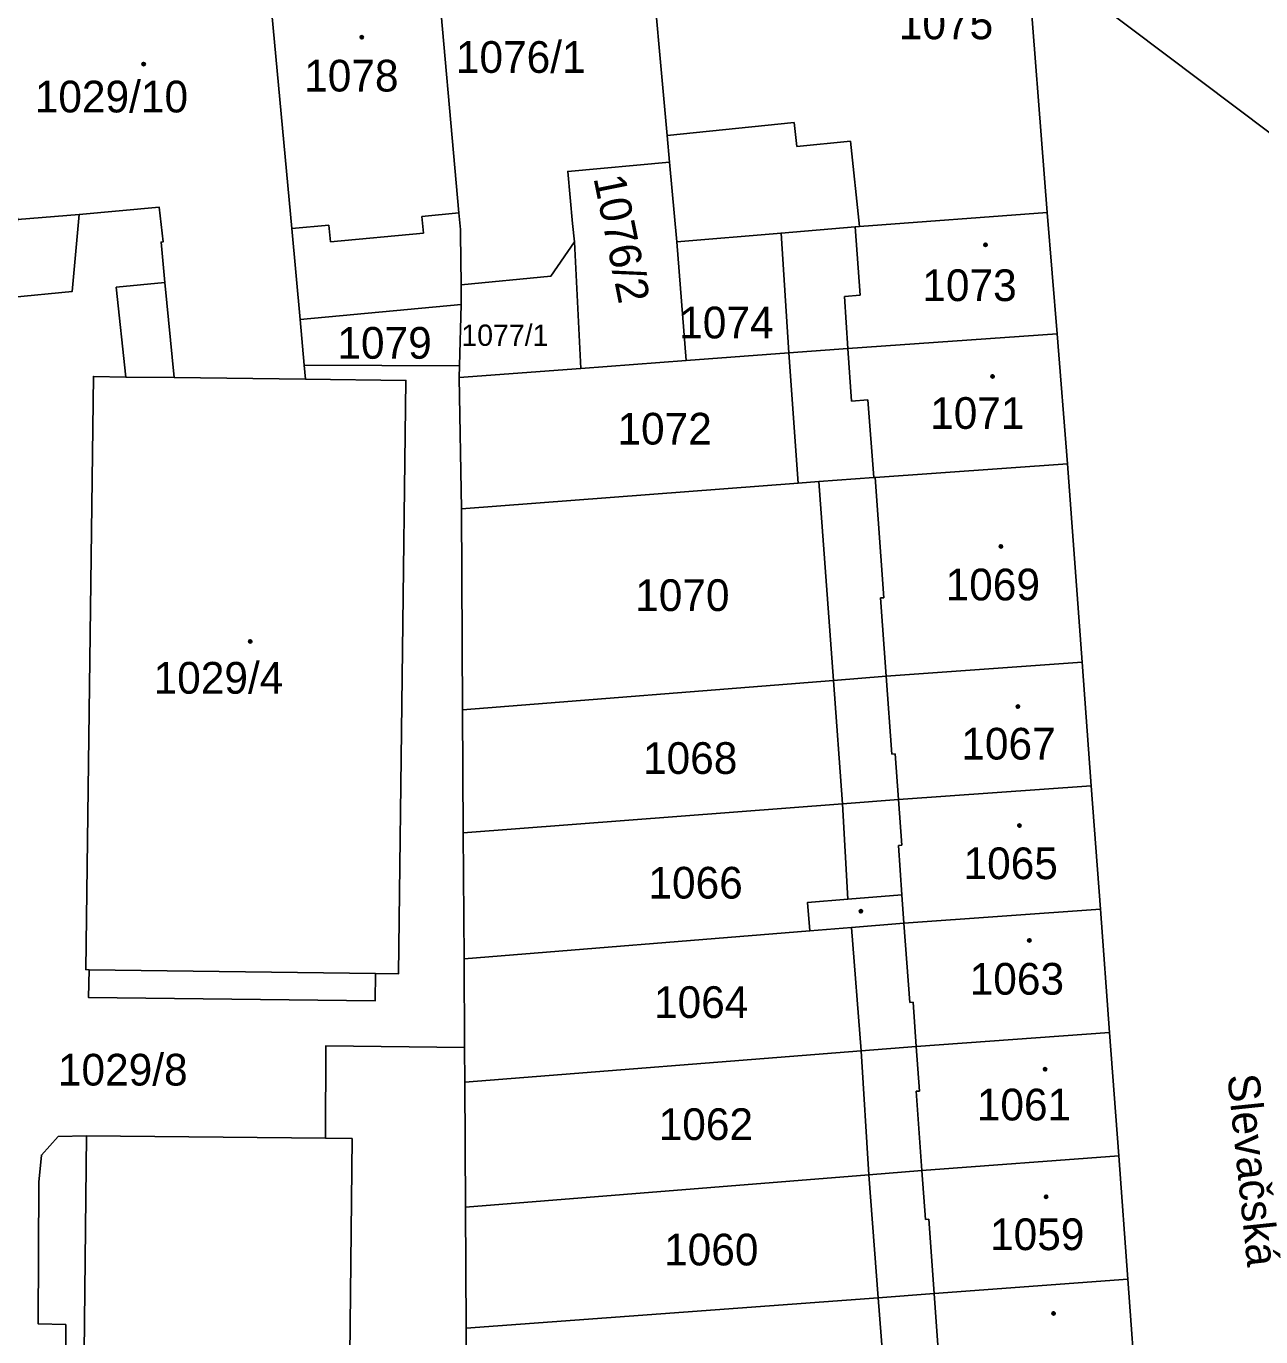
# Model space of a CAD drawing. Extents: x -596233 to -595156, y -1161235 to -1159375.
# Drawn here: x -596152.4 to -596086.2, y -1160957.8 to -1160887.6 of the extents above; entities that cross this region are included whole.
import ezdxf

# ---------------------------------------------------------------- set-up
doc = ezdxf.new("R2010")
doc.units = 0
for name, color, linetype in [('KN_CAR_KR', 7, 'Continuous'), ('KN_KULTURY', 7, 'Continuous'), ('KN_PARC_CIS_POZ', 7, 'Continuous'), ('KN_PARC_CIS_STAV', 7, 'Continuous'), ('KN_PARC_PLOCHA', 7, 'Continuous'), ('KN_ULICE', 7, 'Continuous'), ('parcely_l', 7, 'Continuous')]:
    doc.layers.add(name, color=color, linetype=linetype)

msp = doc.modelspace()

# ---------------------------------------------------------------- linework, layer by layer
at = {"layer": 'KN_CAR_KR'}
for points in [[(-596118.01, -1160893.42), (-596111.2, -1160892.72)], [(-596111.2, -1160892.72), (-596111.06, -1160894.01)], [(-596111.06, -1160894.01), (-596108.18, -1160893.72)], [(-596108.18, -1160893.72), (-596107.71, -1160898.29)], [(-596152.84, -1160897.91), (-596149.52, -1160897.65)], [(-596131.16, -1160897.75), (-596129.17, -1160897.57)], [(-596131.08, -1160898.65), (-596131.16, -1160897.75)], [(-596138.13, -1160898.4), (-596136.14, -1160898.22)], [(-596136.14, -1160898.22), (-596136.06, -1160899.11)], [(-596136.06, -1160899.11), (-596131.08, -1160898.65)], [(-596107.94, -1160898.31), (-596107.67, -1160901.97)], [(-596107.67, -1160901.97), (-596108.5, -1160902.04)], [(-596108.5, -1160902.04), (-596108.32, -1160904.83)], [(-596108.32, -1160904.83), (-596108.14, -1160907.65)], [(-596144.44, -1160906.38), (-596147.02, -1160906.36)], [(-596108.14, -1160907.65), (-596107.25, -1160907.59)], [(-596107.25, -1160907.59), (-596106.94, -1160911.74)], [(-596106.87, -1160911.74), (-596106.4, -1160918.19)], [(-596106.4, -1160918.19), (-596106.58, -1160918.2)], [(-596106.58, -1160918.2), (-596106.28, -1160922.4)], [(-596106.28, -1160922.4), (-596105.97, -1160926.57)], [(-596105.97, -1160926.57), (-596105.79, -1160926.56)], [(-596105.79, -1160926.56), (-596105.62, -1160929)], [(-596105.62, -1160929), (-596105.44, -1160931.45)], [(-596105.44, -1160931.45), (-596105.62, -1160931.46)], [(-596105.43, -1160934.11), (-596105.62, -1160931.46)], [(-596108.33, -1160934.34), (-596105.43, -1160934.11)], [(-596105.43, -1160934.11), (-596105.32, -1160935.63)], [(-596105.01, -1160939.88), (-596105.32, -1160935.63)], [(-596148.99, -1160938.13), (-596133.64, -1160938.33)], [(-596104.83, -1160939.86), (-596105.01, -1160939.88)], [(-596104.66, -1160942.24), (-596104.83, -1160939.86)], [(-596104.48, -1160944.63), (-596104.66, -1160942.24)], [(-596104.66, -1160944.64), (-596104.48, -1160944.63)], [(-596104.36, -1160948.88), (-596104.66, -1160944.64)], [(-596149.51, -1160981.88), (-596149.14, -1160947.02)], [(-596136.33, -1160947.15), (-596134.89, -1160947.17)], [(-596134.89, -1160947.17), (-596135.06, -1160962.12)], [(-596104.17, -1160951.5), (-596104.36, -1160948.88)], [(-596103.99, -1160951.49), (-596104.17, -1160951.5)], [(-596103.7, -1160955.48), (-596103.99, -1160951.49)], [(-596103.5, -1160958.24), (-596103.7, -1160955.48)]]:
    msp.add_lwpolyline(points, dxfattribs=at)
at = {"layer": 'KN_KULTURY'}
for centre, radius in [((-596134.38, -1160888.15), 0.09), ((-596134.38, -1160888.15), 0.0398), ((-596146.07, -1160889.59), 0.09), ((-596146.07, -1160889.59), 0.0398), ((-596100.95, -1160899.27), 0.09), ((-596100.95, -1160899.27), 0.0398), ((-596100.57, -1160906.33), 0.09), ((-596100.57, -1160906.33), 0.0398), ((-596100.12, -1160915.44), 0.09), ((-596100.12, -1160915.44), 0.0398), ((-596140.36, -1160920.53), 0.09), ((-596140.36, -1160920.53), 0.0398), ((-596099.21, -1160924.02), 0.09), ((-596099.21, -1160924.02), 0.0398), ((-596099.13, -1160930.4), 0.09), ((-596099.13, -1160930.4), 0.0398), ((-596107.63, -1160934.99), 0.09), ((-596107.63, -1160934.99), 0.0398), ((-596098.6, -1160936.55), 0.09), ((-596098.6, -1160936.55), 0.0398), ((-596097.76, -1160943.46), 0.09), ((-596097.76, -1160943.46), 0.0398), ((-596097.7, -1160950.29), 0.09), ((-596097.7, -1160950.29), 0.0398), ((-596097.3, -1160956.54), 0.09), ((-596097.3, -1160956.54), 0.0398)]:
    msp.add_circle(centre, radius, dxfattribs=at)
at = {"layer": 'KN_PARC_PLOCHA'}
for points in [[(-596085.86, -1160874.42), (-596010.41, -1160889.08), (-596010.61, -1160897.55), (-596009.92, -1160899.18), (-596006.25, -1160900.53), (-596014.53, -1160904.19), (-596015.11, -1160903.95), (-596018.31, -1160903.34), (-596027.85, -1160901.49), (-596034.91, -1160900.12), (-596042, -1160898.75), (-596049.68, -1160897.26), (-596057.34, -1160895.78), (-596063.22, -1160894.7), (-596069.09, -1160893.61), (-596083.82, -1160894.71), (-596095.08, -1160886.24)], [(-596086.53, -1161045.93), (-596087.62, -1161031.61), (-596088.31, -1161022.58), (-596088.92, -1161014.3), (-596089.41, -1161007.67), (-596089.9, -1161001.04), (-596090.39, -1160994.43), (-596090.88, -1160987.77), (-596091.37, -1160981.19), (-596091.86, -1160974.55), (-596092.35, -1160967.94), (-596092.83, -1160961.32), (-596093.32, -1160954.71), (-596093.81, -1160948.09), (-596094.3, -1160941.49), (-596094.79, -1160934.88), (-596095.28, -1160928.26), (-596095.77, -1160921.64), (-596096.55, -1160911.02), (-596097.11, -1160904.04), (-596097.64, -1160897.55), (-596098.74, -1160883.49)], [(-596095.08, -1160886.24), (-596083.82, -1160894.71), (-596083.26, -1160903.04), (-596082.89, -1160908.46), (-596082.52, -1160913.92), (-596082.13, -1160919.2), (-596081.73, -1160924.55), (-596081.11, -1160932.76), (-596080.52, -1160940.71), (-596079.77, -1160950.72), (-596079.29, -1160957.19), (-596078.81, -1160963.58), (-596078.33, -1160969.99), (-596077.85, -1160976.45), (-596077.37, -1160982.86), (-596076.7, -1160991.84), (-596076.02, -1161000.87), (-596075.35, -1161009.88), (-596075.3, -1161009.88), (-596073.79, -1161031.04), (-596073.72, -1161032.14), (-596072.34, -1161051.17)], [(-596153.2, -1160902.09), (-596149.91, -1160901.78), (-596149.52, -1160897.65), (-596145.23, -1160897.26), (-596145.03, -1160899.12), (-596145.14, -1160899.13), (-596144.93, -1160901.29), (-596147.54, -1160901.55), (-596147.02, -1160906.36), (-596148.76, -1160906.33), (-596149.17, -1160938.12), (-596148.99, -1160938.13), (-596149.03, -1160939.61), (-596133.66, -1160939.79), (-596133.64, -1160938.33), (-596132.42, -1160938.35), (-596132.01, -1160906.54), (-596137.39, -1160906.48), (-596137.46, -1160905.73), (-596129.14, -1160905.76), (-596129.16, -1160906.39), (-596129.04, -1160913.42), (-596128.98, -1160924.19), (-596128.94, -1160930.78), (-596128.9, -1160937.54), (-596128.87, -1160942.29), (-596136.31, -1160942.21), (-596136.33, -1160947.15), (-596149.14, -1160947.02), (-596150.65, -1160947.06), (-596151.55, -1160948.06), (-596151.68, -1160949.51), (-596151.73, -1160957.1), (-596150.25, -1160957.14), (-596150.24, -1160957.5), (-596150.28, -1160961.4)], [(-596150.28, -1160961.4), (-596150.24, -1160957.5), (-596150.25, -1160957.14), (-596151.73, -1160957.1), (-596151.68, -1160949.51), (-596151.55, -1160948.06), (-596150.65, -1160947.06), (-596149.14, -1160947.02), (-596136.33, -1160947.15), (-596136.31, -1160942.21), (-596128.87, -1160942.29), (-596128.86, -1160944.15), (-596128.82, -1160950.85), (-596128.78, -1160957.34), (-596128.74, -1160964.02)]]:
    msp.add_lwpolyline(points, dxfattribs=at)
for points in [[(-596098.74, -1160883.49), (-596097.64, -1160897.55), (-596107.71, -1160898.29), (-596107.94, -1160898.31), (-596111.91, -1160898.65), (-596117.49, -1160899.12), (-596117.88, -1160894.84), (-596118.01, -1160893.42), (-596118.99, -1160882.58), (-596101.95, -1160880.79)], [(-596117.88, -1160894.84), (-596123.34, -1160895.34), (-596123.08, -1160898.14), (-596122.97, -1160899.12), (-596124.24, -1160900.95), (-596129.06, -1160901.42), (-596129.09, -1160898.69), (-596129.09, -1160898.46), (-596129.17, -1160897.57), (-596130.41, -1160883.69), (-596118.99, -1160882.58), (-596118.01, -1160893.42)], [(-596129.06, -1160901.42), (-596129.05, -1160902.48), (-596137.68, -1160903.28), (-596138.13, -1160898.4), (-596139.42, -1160884.56), (-596130.41, -1160883.69), (-596129.17, -1160897.57), (-596129.09, -1160898.46), (-596129.09, -1160898.69)], [(-596137.68, -1160903.28), (-596137.46, -1160905.73), (-596137.39, -1160906.48), (-596144.44, -1160906.38), (-596144.93, -1160901.29), (-596145.14, -1160899.13), (-596145.03, -1160899.12), (-596145.23, -1160897.26), (-596149.52, -1160897.65), (-596149.91, -1160901.78), (-596153.2, -1160902.09), (-596152.84, -1160897.91), (-596153.99, -1160885.97), (-596139.42, -1160884.56), (-596138.13, -1160898.4)], [(-596117.49, -1160899.12), (-596117, -1160905.48), (-596122.64, -1160905.9), (-596122.97, -1160899.12), (-596123.08, -1160898.14), (-596123.34, -1160895.34), (-596117.88, -1160894.84)], [(-596097.11, -1160904.04), (-596108.32, -1160904.83), (-596111.49, -1160905.07), (-596111.91, -1160898.65), (-596107.94, -1160898.31), (-596107.71, -1160898.29), (-596097.64, -1160897.55)], [(-596111.49, -1160905.07), (-596117, -1160905.48), (-596117.49, -1160899.12), (-596111.91, -1160898.65)], [(-596122.64, -1160905.9), (-596129.16, -1160906.39), (-596129.14, -1160905.76), (-596129.05, -1160902.48), (-596129.06, -1160901.42), (-596124.24, -1160900.95), (-596122.97, -1160899.12)], [(-596137.39, -1160906.48), (-596132.01, -1160906.54), (-596132.42, -1160938.35), (-596133.64, -1160938.33), (-596133.66, -1160939.79), (-596149.03, -1160939.61), (-596148.99, -1160938.13), (-596149.17, -1160938.12), (-596148.76, -1160906.33), (-596147.02, -1160906.36), (-596147.54, -1160901.55), (-596144.93, -1160901.29), (-596144.44, -1160906.38)], [(-596129.14, -1160905.76), (-596137.46, -1160905.73), (-596137.68, -1160903.28), (-596129.05, -1160902.48)], [(-596096.55, -1160911.02), (-596106.87, -1160911.74), (-596106.94, -1160911.74), (-596109.88, -1160911.96), (-596110.99, -1160912.05), (-596111.49, -1160905.07), (-596108.32, -1160904.83), (-596097.11, -1160904.04)], [(-596110.99, -1160912.05), (-596129.04, -1160913.42), (-596129.16, -1160906.39), (-596122.64, -1160905.9), (-596117, -1160905.48), (-596111.49, -1160905.07)], [(-596095.77, -1160921.64), (-596106.28, -1160922.4), (-596109.09, -1160922.62), (-596109.88, -1160911.96), (-596106.94, -1160911.74), (-596106.87, -1160911.74), (-596096.55, -1160911.02)], [(-596109.09, -1160922.62), (-596128.98, -1160924.19), (-596129.04, -1160913.42), (-596110.99, -1160912.05), (-596109.88, -1160911.96)], [(-596095.28, -1160928.26), (-596105.62, -1160929), (-596108.61, -1160929.23), (-596109.09, -1160922.62), (-596106.28, -1160922.4), (-596095.77, -1160921.64)], [(-596108.61, -1160929.23), (-596128.94, -1160930.78), (-596128.98, -1160924.19), (-596109.09, -1160922.62)], [(-596094.79, -1160934.88), (-596105.32, -1160935.63), (-596108.13, -1160935.86), (-596110.36, -1160936.04), (-596110.49, -1160934.52), (-596108.33, -1160934.34), (-596108.61, -1160929.23), (-596105.62, -1160929), (-596095.28, -1160928.26)], [(-596110.36, -1160936.04), (-596128.9, -1160937.54), (-596128.94, -1160930.78), (-596108.61, -1160929.23), (-596108.33, -1160934.34), (-596110.49, -1160934.52)], [(-596094.3, -1160941.49), (-596104.66, -1160942.24), (-596107.62, -1160942.47), (-596108.13, -1160935.86), (-596105.32, -1160935.63), (-596094.79, -1160934.88)], [(-596107.62, -1160942.47), (-596128.86, -1160944.15), (-596128.87, -1160942.29), (-596128.9, -1160937.54), (-596110.36, -1160936.04), (-596108.13, -1160935.86)], [(-596093.81, -1160948.09), (-596104.36, -1160948.88), (-596107.2, -1160949.11), (-596107.62, -1160942.47), (-596104.66, -1160942.24), (-596094.3, -1160941.49)], [(-596107.2, -1160949.11), (-596128.82, -1160950.85), (-596128.86, -1160944.15), (-596107.62, -1160942.47)], [(-596093.32, -1160954.71), (-596103.7, -1160955.48), (-596106.7, -1160955.7), (-596107.2, -1160949.11), (-596104.36, -1160948.88), (-596093.81, -1160948.09)], [(-596106.7, -1160955.7), (-596128.78, -1160957.34), (-596128.82, -1160950.85), (-596107.2, -1160949.11)], [(-596092.83, -1160961.32), (-596103.39, -1160962.13), (-596106.18, -1160962.34), (-596106.7, -1160955.7), (-596103.7, -1160955.48), (-596093.32, -1160954.71)], [(-596106.18, -1160962.34), (-596128.74, -1160964.02), (-596128.78, -1160957.34), (-596106.7, -1160955.7)]]:
    msp.add_lwpolyline(points, close=True, dxfattribs=at)
at = {"layer": 'parcely_l'}
for points in [[(-596117.88, -1160894.84), (-596118.01, -1160893.42), (-596118.99, -1160882.58)], [(-596129.06, -1160901.42), (-596129.09, -1160898.69), (-596129.09, -1160898.46), (-596129.17, -1160897.57), (-596130.41, -1160883.69)], [(-596098.74, -1160883.49), (-596097.64, -1160897.55)], [(-596139.42, -1160884.56), (-596138.13, -1160898.4), (-596137.68, -1160903.28)], [(-596095.08, -1160886.24), (-596083.82, -1160894.71)], [(-596117.88, -1160894.84), (-596123.34, -1160895.34), (-596123.08, -1160898.14), (-596122.97, -1160899.12)], [(-596117.49, -1160899.12), (-596117.88, -1160894.84)], [(-596144.93, -1160901.29), (-596145.14, -1160899.13), (-596145.03, -1160899.12), (-596145.23, -1160897.26), (-596149.52, -1160897.65), (-596149.91, -1160901.78), (-596153.2, -1160902.09)], [(-596097.64, -1160897.55), (-596107.71, -1160898.29), (-596107.94, -1160898.31), (-596111.91, -1160898.65)], [(-596097.64, -1160897.55), (-596097.11, -1160904.04)], [(-596111.91, -1160898.65), (-596117.49, -1160899.12)], [(-596111.49, -1160905.07), (-596111.91, -1160898.65)], [(-596122.97, -1160899.12), (-596124.24, -1160900.95), (-596129.06, -1160901.42)], [(-596122.64, -1160905.9), (-596122.97, -1160899.12)], [(-596117.49, -1160899.12), (-596117, -1160905.48)], [(-596144.93, -1160901.29), (-596147.54, -1160901.55), (-596147.02, -1160906.36), (-596148.76, -1160906.33), (-596149.17, -1160938.12), (-596148.99, -1160938.13), (-596149.03, -1160939.61), (-596133.66, -1160939.79), (-596133.64, -1160938.33), (-596132.42, -1160938.35), (-596132.01, -1160906.54), (-596137.39, -1160906.48)], [(-596137.39, -1160906.48), (-596144.44, -1160906.38), (-596144.93, -1160901.29)], [(-596129.06, -1160901.42), (-596129.05, -1160902.48)], [(-596137.68, -1160903.28), (-596129.05, -1160902.48)], [(-596129.05, -1160902.48), (-596129.14, -1160905.76)], [(-596137.68, -1160903.28), (-596137.46, -1160905.73)], [(-596097.11, -1160904.04), (-596108.32, -1160904.83), (-596111.49, -1160905.07)], [(-596097.11, -1160904.04), (-596096.55, -1160911.02)], [(-596137.46, -1160905.73), (-596137.39, -1160906.48)], [(-596137.46, -1160905.73), (-596129.14, -1160905.76)], [(-596122.64, -1160905.9), (-596117, -1160905.48)], [(-596117, -1160905.48), (-596111.49, -1160905.07)], [(-596111.49, -1160905.07), (-596110.99, -1160912.05)], [(-596129.14, -1160905.76), (-596129.16, -1160906.39)], [(-596129.16, -1160906.39), (-596122.64, -1160905.9)], [(-596129.16, -1160906.39), (-596129.04, -1160913.42)], [(-596109.88, -1160911.96), (-596106.94, -1160911.74), (-596106.87, -1160911.74), (-596096.55, -1160911.02)], [(-596096.55, -1160911.02), (-596095.77, -1160921.64)], [(-596110.99, -1160912.05), (-596129.04, -1160913.42)], [(-596110.99, -1160912.05), (-596109.88, -1160911.96)], [(-596109.09, -1160922.62), (-596109.88, -1160911.96)], [(-596129.04, -1160913.42), (-596128.98, -1160924.19)], [(-596109.09, -1160922.62), (-596106.28, -1160922.4), (-596095.77, -1160921.64)], [(-596095.77, -1160921.64), (-596095.28, -1160928.26)], [(-596128.98, -1160924.19), (-596109.09, -1160922.62)], [(-596108.61, -1160929.23), (-596109.09, -1160922.62)], [(-596128.94, -1160930.78), (-596128.98, -1160924.19)], [(-596095.28, -1160928.26), (-596105.62, -1160929), (-596108.61, -1160929.23)], [(-596095.28, -1160928.26), (-596094.79, -1160934.88)], [(-596128.94, -1160930.78), (-596108.61, -1160929.23)], [(-596108.61, -1160929.23), (-596108.33, -1160934.34), (-596110.49, -1160934.52), (-596110.36, -1160936.04)], [(-596128.9, -1160937.54), (-596128.94, -1160930.78)], [(-596094.79, -1160934.88), (-596105.32, -1160935.63), (-596108.13, -1160935.86)], [(-596094.3, -1160941.49), (-596094.79, -1160934.88)], [(-596108.13, -1160935.86), (-596110.36, -1160936.04)], [(-596108.13, -1160935.86), (-596107.62, -1160942.47)], [(-596110.36, -1160936.04), (-596128.9, -1160937.54)], [(-596128.9, -1160937.54), (-596128.87, -1160942.29)], [(-596107.62, -1160942.47), (-596104.66, -1160942.24), (-596094.3, -1160941.49)], [(-596094.3, -1160941.49), (-596093.81, -1160948.09)], [(-596128.87, -1160942.29), (-596136.31, -1160942.21), (-596136.33, -1160947.15), (-596149.14, -1160947.02), (-596150.65, -1160947.06), (-596151.55, -1160948.06), (-596151.68, -1160949.51), (-596151.73, -1160957.1), (-596150.25, -1160957.14), (-596150.24, -1160957.5), (-596150.28, -1160961.4), (-596150.29, -1160961.76), (-596151.77, -1160961.7), (-596151.89, -1160971.6), (-596151.51, -1160977.8), (-596150.47, -1160977.79), (-596150.46, -1160978.18), (-596150.5, -1160981.89), (-596149.51, -1160981.88), (-596149.56, -1160984.42), (-596151.01, -1160984.42), (-596151.12, -1160993.47), (-596151.17, -1161002.14), (-596148.24, -1161001.67)], [(-596128.86, -1160944.15), (-596128.87, -1160942.29)], [(-596128.86, -1160944.15), (-596107.62, -1160942.47)], [(-596107.62, -1160942.47), (-596107.2, -1160949.11)], [(-596128.82, -1160950.85), (-596128.86, -1160944.15)], [(-596093.81, -1160948.09), (-596104.36, -1160948.88), (-596107.2, -1160949.11)], [(-596093.32, -1160954.71), (-596093.81, -1160948.09)], [(-596107.2, -1160949.11), (-596128.82, -1160950.85)], [(-596106.7, -1160955.7), (-596107.2, -1160949.11)], [(-596128.82, -1160950.85), (-596128.78, -1160957.34)], [(-596093.32, -1160954.71), (-596103.7, -1160955.48), (-596106.7, -1160955.7)], [(-596092.83, -1160961.32), (-596093.32, -1160954.71)], [(-596128.78, -1160957.34), (-596106.7, -1160955.7)], [(-596106.7, -1160955.7), (-596106.18, -1160962.34)], [(-596128.74, -1160964.02), (-596128.78, -1160957.34)]]:
    msp.add_lwpolyline(points, dxfattribs=at)

# ---------------------------------------------------------------- texts
at = {"layer": 'KN_PARC_CIS_POZ'}
msp.add_text('1076/2', height=1.7, rotation=281.46152, dxfattribs=at).set_placement((-596121.9671, -1160895.6894))
for s, height, p in [('1074', 1.7, (-596117.3666, -1160904.29)), ('1077/1', 1.14, (-596129.04, -1160904.69)), ('1079', 1.7, (-596135.6866, -1160905.38)), ('1072', 1.7, (-596120.6766, -1160909.98)), ('1070', 1.7, (-596119.7266, -1160918.9)), ('1068', 1.7, (-596119.3066, -1160927.63)), ('1066', 1.7, (-596119.0166, -1160934.31)), ('1064', 1.7, (-596118.7166, -1160940.71)), ('1029/8', 1.7, (-596150.6666, -1160944.33)), ('1062', 1.7, (-596118.4666, -1160947.25)), ('1060', 1.7, (-596118.1766, -1160953.97))]:
    msp.add_text(s, height=height, dxfattribs=at).set_placement(p)
at = {"layer": 'KN_PARC_CIS_STAV'}
for s, p in [('1075', (-596105.5966, -1160888.26)), ('1076/1', (-596129.3366, -1160890.06)), ('1078', (-596137.4666, -1160891.06)), ('1029/10', (-596151.9066, -1160892.18)), ('1073', (-596104.3366, -1160902.29)), ('1071', (-596103.9166, -1160909.14)), ('1069', (-596103.0866, -1160918.33)), ('1029/4', (-596145.5366, -1160923.33)), ('1067', (-596102.2466, -1160926.86)), ('1065', (-596102.1266, -1160933.27)), ('1063', (-596101.7966, -1160939.46)), ('1061', (-596101.4166, -1160946.2)), ('1059', (-596100.7066, -1160953.15))]:
    msp.add_text(s, height=1.7, dxfattribs=at).set_placement(p)
at = {"layer": 'KN_ULICE'}
msp.add_text('Slevačská', height=1.7, rotation=275.98768, dxfattribs=at).set_placement((-596087.9884, -1160943.7836))

doc.saveas('drawing.dxf')
